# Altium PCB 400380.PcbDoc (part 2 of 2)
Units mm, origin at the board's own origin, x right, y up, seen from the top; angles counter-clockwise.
Board outline 48.52 x 76.32 mm, 4 copper layers (Top Layer, Mid-Layer 1, Mid-Layer 2, Bottom Layer), stack 1.542 mm thick; 122 components, 105 nets, 497 pads, 444 vias.
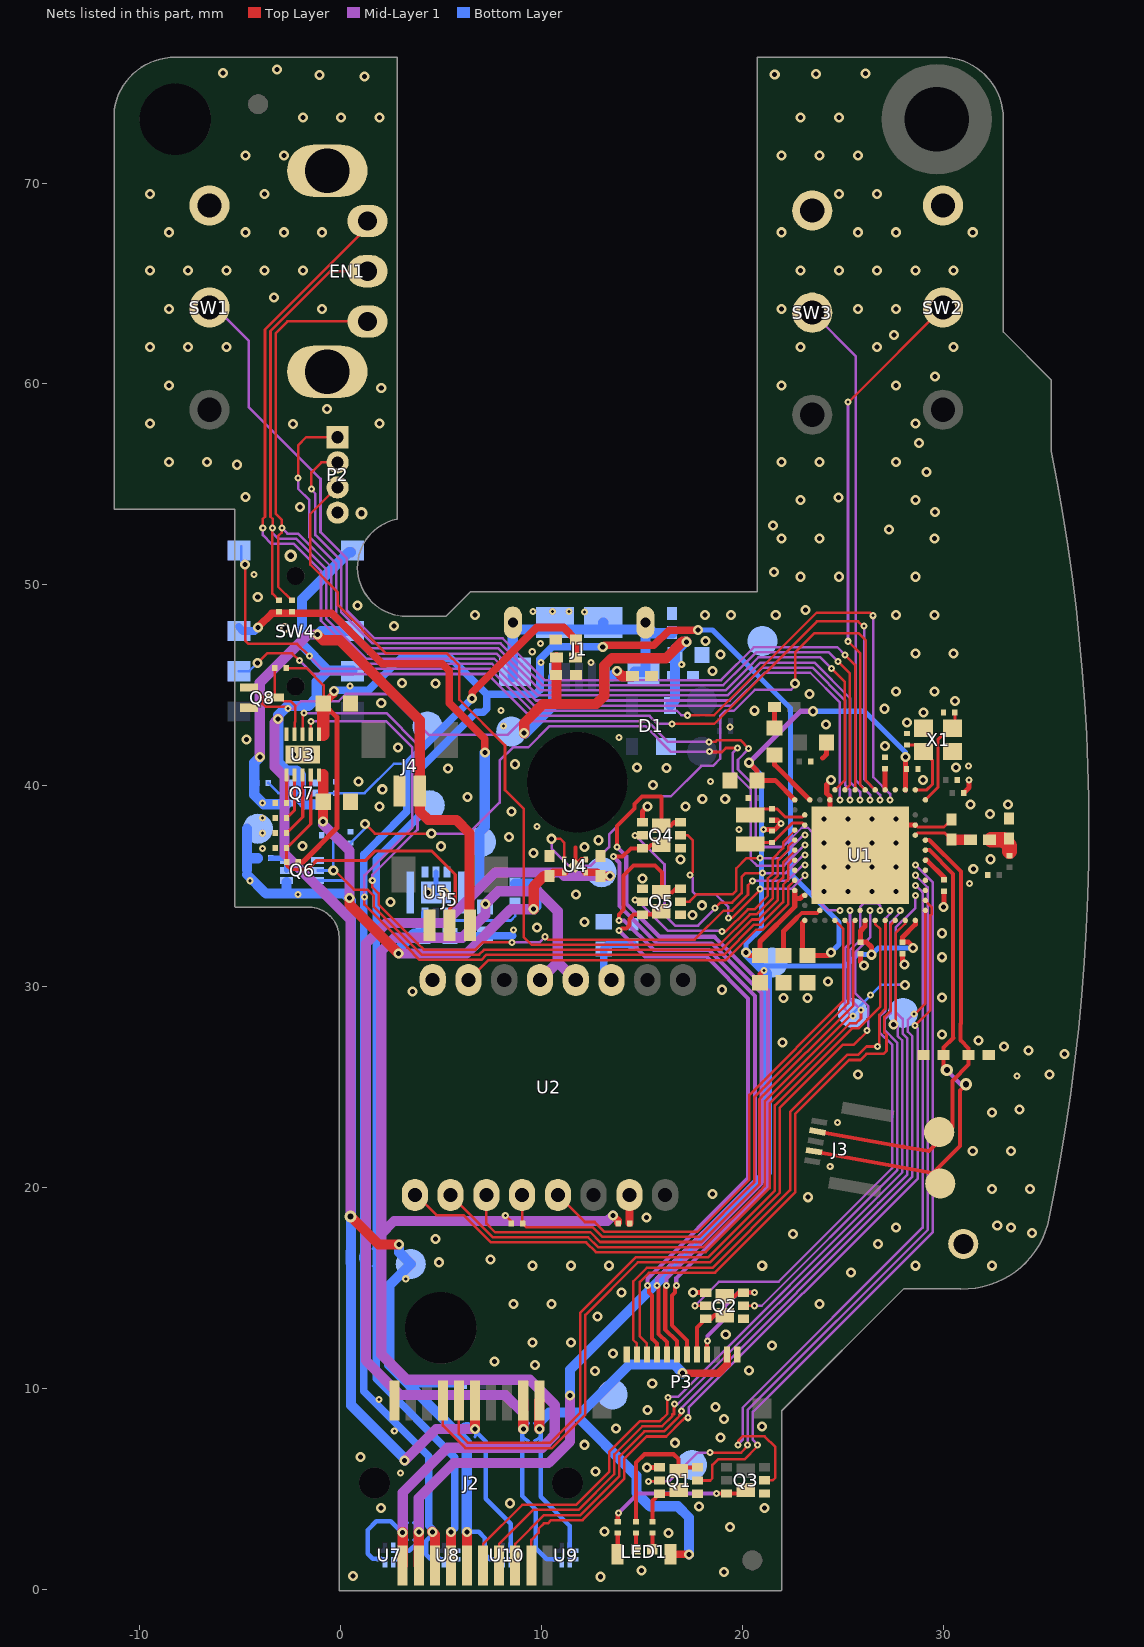
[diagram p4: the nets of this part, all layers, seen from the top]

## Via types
v1: diameter 0.5, hole 0.25, Top Layer to Bottom Layer, tented both sides, 311 vias
v2: diameter 0.35, hole 0.15, Top Layer to Mid-Layer 1, tented both sides, 102 vias
v3: diameter 0.35, hole 0.15, Top Layer to Mid-Layer 1, tented top, 26 vias
v4: diameter 0.61, hole 0.305, Top Layer to Mid-Layer 1, tented both sides, 3 vias
v5: diameter 0.61, hole 0.305, Top Layer to Bottom Layer, tented both sides, 2 vias

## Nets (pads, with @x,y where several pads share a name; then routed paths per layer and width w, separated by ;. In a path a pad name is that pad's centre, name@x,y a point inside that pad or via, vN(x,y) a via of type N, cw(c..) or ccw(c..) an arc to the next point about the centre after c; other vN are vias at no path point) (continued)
GND: C1.2 C2.2 C3.1 C4.1 C5.2 C6.2 C7.2 C8.2 C9.2 C10.1 C11.2 C12.2 C13.2 C14.2 C15.1 C16.2 C17.2 C18.2 C19.1 C20.2 C21.2 C22.2 C23.2 C24.1 C25.1 C26.1 C29.1 C30.1 C31.1 C32.1 C33.2 C34.1 C44.2 C45.2 C48.1 C49.1 D1.1 EN1.4 EN1.5 FB2.2 FB3.2 J2.20 J4.1 J5.1 P2.4 P3.1 P3.12 Q1.1 Q1.4 Q2.1 Q2.4 Q3.1 Q4.1 Q4.4 Q5.1 Q5.4 Q6.1 Q7.1 Q8.2 R4.1 R10.1 R11.1 R16.1 R26.2 R28.2 SW1.2 SW2.2 SW3.2 TP4.1 TP9.1 TP22.1 U1.74 U1.B7 U1.F23 U2.8 U3.5 U3.11 U4.2 U4.5 U5.2 U5.9 U7.2 U8.2 U9.2 U10.2 X1.2 X1.4 | length 23.8
  Top Layer w0.145: U1.F23@28.612,38.047 28.717,37.942 30.033,37.942 C3.1@30.413,38.323
  Top Layer w0.203: U4.5@11.684,36.014 11.693,36.023 11.693,36.912 11.709,36.928
  Top Layer w0.25: 24,41.373 24.187,41.561 C15.1@24.187,42.157 C15.1@24.187,42.411 ; v1(24.409,40.281) 24.204,40.076 24.204,39.629 24.362,39.471 U1.B7@24.362,39.297 24.362,38.047 v1(25.262,37.147) U1.74@25.862,36.547 v1(26.462,37.147) 27.362,38.047 U1.F23@28.612,38.047
  Top Layer w0.254: U4.5@11.693,36.023 12.009,36.339 U4.2@12.219,36.339 ; Q4.1@15.034,38.185 15.034,38.729 v1(15.279,38.974) ; v1(15.26,6.074) Q1.4@15.887,6.074 ; v1(17.551,14.783) 18.174,14.783 Q2.1@18.181,14.776 ; C6.2@20.88,30.197 20.88,30.62 21.067,30.807 v3(21.082,30.807) ; v3(21.057,37.817) 21.613,37.817 v3(21.921,38.125) 21.761,38.284 C17.2@21.489,38.284 ; C7.2@25.883,31.645 25.883,31.241 v1(26.061,31.064) ; C8.2@27.977,31.645 27.977,31.216 v1(28.078,31.114) ; v1(30.013,33.973) 30.037,33.997 C9.2@30.037,34.745 ; C10.1@31.019,39.646 31.293,39.92 v3(31.293,40.281)
  Bottom Layer w0.254: U5.9@4.75,34.693 U5.2@4.75,35.718
  Bottom Layer w0.381: C48.1@5.45,32.534 8.573,32.534
  other v1: 12.95,0.635 0.635,0.683 19.089,0.874 14.992,0.937 16.327,2.814 13.138,2.891 19.38,3.121 21.107,4.061 2.025,4.064 17.855,4.123 8.433,4.293 12.7,5.864 0.991,6.589 12.141,7.203 16.653,7.303 18.926,7.569 13.716,8.024 20.98,8.121 19.089,8.494 15.291,8.938 18.669,9.09 15.519,10.262 12.675,10.871 20.345,10.893 9.674,11.171 7.671,11.351 13.575,11.735 21.488,12.138 9.564,12.304 11.469,12.304 19.178,12.7 12.802,13.589 8.611,14.209 10.516,14.209 23.851,14.209 13.979,14.783 25.4,15.773 9.564,16.114 11.469,16.114 13.374,16.114 20.994,16.114 28.614,16.114 32.424,16.114 4.913,16.286 7.468,16.434 26.746,17.193 4.724,17.433 22.53,17.688 34.417,17.751 27.661,18.019 33.376,18.019 32.69,18.107 15.228,18.517 23.266,19.523 18.517,19.685 32.424,19.924 34.329,19.924 31.471,21.829 33.376,21.829 32.424,23.734 33.807,23.898 25.756,25.639 35.281,25.639 36.043,26.641 34.239,26.819 33.02,27.022 21.996,27.225 31.75,27.327 29.947,27.632 22.048,29.443 23.237,29.443 29.947,29.461 3.581,29.766 18.999,29.849 24.258,30.251 29.947,31.467 29.947,32.661 9.784,32.951 12.148,33.226 17.529,33.579 18.001,34.054 2.499,34.214 11.735,34.595 4.35,34.693 5.15,34.693 24.062,34.747 25.262,34.747 26.462,34.747 27.662,34.747 15.034,35.376 31.496,35.862 24.062,35.947 25.262,35.947 26.462,35.947 27.662,35.947 16.916,36.335 32.36,36.344 9.621,36.649 12.141,36.954 5.004,36.991 -1.88,37.008 24.062,37.147 27.662,37.147 12.852,37.289 8.382,37.462 24.062,38.347 25.262,38.347 26.462,38.347 27.662,38.347 32.335,38.587 8.509,38.723 1.944,38.974 17.184,38.974 31.369,39.062 33.224,39.065 18.009,39.341 19.152,39.341 6.325,39.446 2.083,39.827 15.559,40.046 0.901,40.208 28.985,40.279 5.359,40.85 16.231,40.879 14.757,40.916 30.633,40.919 8.686,41.072 -2.339,41.548 -1.448,41.556 2.855,41.91 27.102,41.986 -4.673,42.313 24.156,43.052 28.198,43.154 29.02,43.637 20.599,43.736 27.076,43.834 2.032,44.111 30.584,44.218 23.343,44.574 27.661,44.689 29.566,44.689 4.729,45.082 3.075,45.116 18.517,45.717 18.923,46.53 28.614,46.594 30.519,46.594 18.161,47.215 -2.769,47.85 2.667,47.952 6.706,48.499 18.136,48.499 19.431,48.511 21.666,48.511 27.661,48.499 29.566,48.499 23.139,48.739 0.852,48.968 -4.115,49.403 22.899,50.404 24.804,50.404 28.614,50.404 21.59,50.644 21.946,52.309 23.851,52.309 29.566,52.309 27.305,52.753 21.539,52.956 29.591,53.616 -2.003,53.877 22.899,54.214 28.614,54.214 24.79,54.353 -4.724,54.378 29.159,55.623 -5.156,55.978 -8.534,56.119 -6.629,56.119 21.946,56.119 23.851,56.119 27.661,56.119 28.804,57.071 -2.362,58.01 -9.486,58.024 1.944,58.024 28.614,58.024 -0.663,58.75 2.032,59.788 -8.534,59.929 21.946,59.929 27.661,59.929 29.591,60.373 -9.486,61.834 -7.581,61.834 -5.676,61.834 22.899,61.834 26.709,61.834 30.519,61.834 27.559,62.43 -8.534,63.739 -0.914,63.739 21.946,63.739 25.756,63.739 27.661,63.739 -3.316,64.31 -9.486,65.644 -7.581,65.644 -5.676,65.644 -3.771,65.644 -1.866,65.644 22.899,65.644 24.804,65.644 26.709,65.644 28.614,65.644 30.519,65.644 -8.534,67.549 -4.724,67.549 -2.819,67.549 -0.914,67.549 21.946,67.549 25.756,67.549 27.661,67.549 31.471,67.549 -9.486,69.454 -3.771,69.454 24.804,69.454 26.709,69.454 -4.724,71.359 -2.819,71.359 21.946,71.359 23.851,71.359 25.756,71.359 -1.866,73.264 0.039,73.264 1.944,73.264 22.899,73.264 24.804,73.264 1.194,75.308 -1.041,75.384 21.615,75.409 23.673,75.435 26.137,75.46 -5.842,75.486 -3.15,75.638
  other v2: 3,5.8 2.68,7.896 1.915,9.446 3.251,15.465 24.378,21.052 24.748,23.232 33.681,25.561 26.391,29.591 8.611,32.817 -2.108,34.595 31.319,35.128 -4.496,35.274 -3.886,36.888 -3.886,37.639 9.779,37.973 -3.886,38.389 -3.886,39.139 18.416,40.205 13.859,42.393 19.392,42.916 8.128,42.979 8,43.758 0.483,44.974 16.987,46.045 9.988,46.142 12.472,46.145 9.547,46.671 9.952,47.081 12.143,48.639 9.594,48.666 10.564,48.679 11.374,48.666 -4.293,50.517
  other v3: 19.837,37.821 31.267,40.992
  other v5: -2.474,51.447 1.046,53.565
LED2_B_LOW: P3.4 Q5.3 | length 30.7
  Top Layer w0.203: v2(13.868,32.788) 13.897,32.788 14.005,32.896 14.226,32.896 14.39,33.059 14.39,33.379 14.597,33.586 Q5.3@15.034,33.586 15.476,33.586 15.651,33.761 Q5.3@15.979,33.761 Q5.3@16.129,33.761 ; v2(15.284,15.135) 15.358,15.062 15.358,14.774 15.505,14.627 15.505,12.482 15.75,12.237 P3.4@15.75,11.7
  Mid-Layer 1 w0.203: v2(13.868,32.788) 15.16,31.496 18.209,31.496 18.336,31.369 20.295,29.41 20.295,20.473 15.284,15.463 v2(15.284,15.135)
LED2_G_LOW: P3.5 Q5.6 | length 35
  Top Layer w0.203: v2(13.868,33.299) 13.868,33.604 14.097,33.833 14.097,35.528 14.592,36.023 15.663,36.023 16.002,35.684 16.002,34.838 16.144,34.696 16.504,34.696 16.693,34.886 Q5.6@16.924,34.886 Q5.6@17.074,34.886 ; v2(15.761,15.135) 15.835,15.062 15.835,12.725 16.25,12.31 P3.5@16.25,11.7
  Mid-Layer 1 w0.203: v2(13.868,33.299) 14.122,33.299 15.596,31.826 18.345,31.826 18.472,31.699 20.625,29.547 20.625,20.336 20.431,20.143 15.761,15.473 v2(15.761,15.135)
LED2_R_LOW: P3.6 Q4.3 | length 34.3
  Top Layer w0.203: v2(13.589,36.474) 14.042,36.474 14.453,36.885 Q4.3@15.034,36.885 15.294,36.885 15.469,37.06 Q4.3@15.979,37.06 ; v2(16.238,15.135) 16.165,15.062 16.165,12.95 16.75,12.365 P3.6@16.75,11.7
  Mid-Layer 1 w0.203: v2(13.589,36.474) 13.894,36.17 13.894,34.016 15.754,32.156 18.482,32.156 18.609,32.029 20.955,29.684 20.955,20.2 16.238,15.483 v2(16.238,15.135)
LED3_B_LOW: P3.7 Q4.6 | length 38.7
  Top Layer w0.203: v2(13.767,36.957) 13.767,37.998 14.636,38.868 14.636,39.096 15.011,39.472 15.951,39.472 15.979,39.444 Q4.6@15.979,38.01 16.439,38.01 16.614,38.185 Q4.6@16.868,38.185 ; v2(16.716,15.135) 16.642,15.062 16.642,14.774 16.495,14.627 16.495,13.15 17.25,12.395 P3.7@17.25,11.7
  Mid-Layer 1 w0.203: v2(13.767,36.957) 14.224,36.5 14.224,34.153 15.891,32.487 18.619,32.487 18.746,32.36 21.285,29.82 21.285,20.063 16.716,15.493 v2(16.716,15.135)
NetC3_2: C3.2 L1.1 U1.H23 | length 2.9
  Top Layer w0.145: U1.H23@28.612,37.547 28.717,37.652 30.082,37.652 C3.2@30.416,37.318
  Top Layer w0.508: C3.2@30.416,37.318 L1.1@31.31,37.318
NetC9_1: C9.1 U1.N24 | length 1.4
  Top Layer w0.25: U1.N24@29.112,36.297 29.188,36.297 30.037,35.449 C9.1@30.037,35.315
NetC13_1: C13.1 U1.A18 | length 1
  Top Layer w0.25: U1.A18@27.112,39.797 C13.1@27.112,40.845
NetC20_1: C20.1 U1.AC5 | length 3.5
  Top Layer w0.184: 22.704,33.42 22.957,33.672 23.736,33.672 U1.AC5@23.862,33.797
  Top Layer w0.25: C20.1@22.062,31.547 22.062,32.777 22.704,33.42
NetC22_1: C22.1 U3.6 | length 1.4
  Top Layer w0.152: C22.1@-2.682,39.137 -2.676,39.143 U3.6@-2.676,40.541
NetC24_2: C24.2 C25.2 U2.3 | length 3.3
  Bottom Layer w0.381: U2.3@13.494,30.337 13.106,30.724 C25.2@13.106,31.885 13.332,32.11 C24.2@14.58,32.11
NetC29_2: C29.2 C31.2 C32.2 D1.4 FB1.1 J1.1 TP1.1 | length 20.5
  Top Layer w0.508: v1(9.144,42.618) 9.144,43.122 10.098,44.076 12.737,44.076 13.132,44.472 13.132,45.974 13.51,46.352 16.205,46.352 17.018,47.165 v1(17.221,47.165) ; 10.755,44.102 FB1.1@10.755,46.393
  Bottom Layer w0.508: v1(9.144,42.618) 9.195,42.618 10.592,44.015 J1.1@10.592,45.408 ; D1.4@16.411,44.004 16.648,44.24 16.648,46.794 16.777,46.923 16.918,46.923 17.159,47.165 v1(17.221,47.165)
NetFB2_1: FB2.1 J1.5 | length 1.6
  Top Layer w0.508: v1(13.767,45.702) 14.021,45.448 14.522,45.448 FB2.1@14.536,45.463
  Bottom Layer w0.508: J1.5@13.181,45.448 13.513,45.448 v1(13.767,45.702)
NetFB3_1: FB3.1 J1.6@8.581,48.123 J1.6@8.681,45.673 J1.6@10.681,48.123 J1.6@13.081,48.123 J1.6@15.081,45.673 J1.6@15.181,48.123 | length 13.6
  Bottom Layer w0.508: J1.6@8.579,45.423 8.579,47.773 J1.6@13.081,47.773 ; J1.6@13.081,48.123 J1.6@13.081,47.773 ; J1.6@14.649,45.673 J1.6@15.081,45.673 15.181,45.773 15.181,47.992 ccw(c15.483,48.027) J1.6@15.483,47.723 ; J1.6@15.179,47.773 J1.6@13.081,47.773 ; J1.6@15.483,47.596 FB3.1@16.51,47.596
NetL2_1: L2.1 L3.2 | length 1.1
  Top Layer w0.25: L2.1@21.612,42.872 L3.2@21.612,43.922
NetL2_2: L2.2 U1.B3 | length 2.9
  Top Layer w0.25: L2.2@21.612,41.522 21.612,41.047 U1.B3@23.362,39.297
NetLED1_1: LED1.1 R9.2 | length 0.7
  Top Layer w0.127: LED1.1@15.516,2.131 LED1.1@15.529,2.131
  Top Layer w0.203: LED1.1@15.529,2.131 R9.2@15.529,2.811
NetLED1_2: LED1.2 R8.2 | length 0.8
  Top Layer w0.203: LED1.2@14.704,2.004 14.716,2.017 R8.2@14.716,2.811
NetLED1_3: LED1.3 R7.2 | length 1.1
  Top Layer w0.203: LED1.3@13.789,1.75 13.802,1.763 R7.2@13.802,2.811
NetP3_8: P3.8 Q2.3 | length 3
  Top Layer w0.203: P3.8@17.75,11.7 17.75,13.045 Q2.3@18.181,13.476 18.454,13.476 18.629,13.651 Q2.3@19.126,13.651
NetP3_9: P3.9 Q2.6 | length 6.1
  Top Layer w0.203: P3.9@18.25,11.7 18.25,12.353 v2(18.263,12.365) ; Q2.6@19.126,14.601 19.63,14.601 19.805,14.776 Q2.6@20.071,14.776 20.078,14.783 v2(20.599,14.783)
  Mid-Layer 1 w0.203: v2(18.263,12.365) 18.263,12.609 19.126,13.473 19.126,14.097 19.812,14.783 v2(20.599,14.783)
NetQ1_3: Q1.3 R8.1 | length 6.9
  Top Layer w0.203: R8.1@14.716,3.381 14.716,6.318 15.129,6.731 16.586,6.731 16.832,6.485 Q1.3@16.832,5.899 17.007,6.074 Q1.3@17.777,6.074
NetQ1_6: Q1.6 R9.1 | length 2.1
  Top Layer w0.203: R9.1@15.529,3.381 15.529,4.416 Q1.6@15.887,4.774 ; Q1.6@15.887,4.744 Q1.6@16.455,4.744
NetQ3_6: Q3.6 R7.1 | length 7.3
  Top Layer w0.203: R7.1@13.802,3.381 13.802,3.775 v2(13.837,3.81) ; v2(18.72,4.78) 19.179,4.78 19.2,4.801 Q3.6@19.221,4.78 19.991,4.78 Q3.6@20.166,4.955
  Mid-Layer 1 w0.203: v2(13.837,3.81) 14.807,4.78 v2(18.72,4.78)
NetQ6_3: Q6.3 R27.1 | length 2.2
  Bottom Layer w0.127: Q6.3@-1.13,35.285 0.36,35.285 0.494,35.419 R27.1@0.494,35.983
NetQ6_5: Q6.5 Q6.6 R24.2 | length 1.3
  Bottom Layer w0.254: R24.2@-3.474,36.395 -2.79,36.395 Q6.6@-2.68,36.285 Q6.5@-2.68,35.785
NetQ7_5: Q7.5 Q7.6 R14.1 | length 1.6
  Bottom Layer w0.127: R14.1@-3.586,40.139 -3.081,39.634 Q7.5@-2.693,39.634 Q7.6@-2.693,40.134 Q7.6@-2.698,40.139
NetQ8_3: Q8.3 R15.1 U3.4 | length 4.1
  Top Layer w0.127: R15.1@-3.266,45.857 -3.266,44.439 -3.27,44.435 -3.048,44.435 -2.822,44.208 -2.474,44.208 -2.472,44.206 -2.465,44.206 -2.251,43.992 -2.251,43.18 -2.276,43.155 U3.4@-2.276,42.571
NetR2_1: R2.1 U2.15 | length 1.4
  Top Layer w0.127: R2.1@14.383,18.233 R2.1@14.407,18.209
  Top Layer w0.381: R2.1@14.383,18.233 U2.15@14.383,19.637
NetR10_2: R10.2 U3.7 | length 2.3
  Top Layer w0.152: R10.2@-2.682,38.389 -2.276,38.795 U3.7@-2.276,40.541
NetR11_2: R11.2 U3.8 | length 3.2
  Top Layer w0.152: R11.2@-2.682,37.641 -1.876,38.447 U3.8@-1.876,40.541
NetR13_1: R13.1 U5.4 | length 4.2
  Bottom Layer w0.127: U5.4@5.3,33.668 5.672,33.296 8.48,33.296 8.691,33.507 R13.1@8.691,34.036
NetU5_1: U5.1 U5.7
NTC: J5.2 R3.1 R4.2 U3.9 | length 17
  Top Layer w0.152: U3.9@-1.476,40.541 -1.476,38.099 R4.2@-2.682,36.893 -2.682,36.216 R3.1@-2.673,36.207 -2.673,36.023 -2.489,35.839 -1.627,35.839 -1.177,36.289 1.262,36.289 1.735,36.761 4.535,36.761 5.715,35.581 5.715,34.172 5.44,33.897 5.44,33.067 J5.2@5.44,33.057
P0.00/XL1: C17.1 U1.D2 X2.1 | length 3.1
  Top Layer w0.145: X2.1@20.397,38.545 20.706,38.854 C17.1@21.489,38.854 21.725,38.854 22.137,38.442 23.007,38.442 U1.D2@23.112,38.547
P0.01/XL2: C18.1 U1.F2 X2.2 | length 3.2
  Top Layer w0.145: X2.2@20.397,37.095 20.478,37.177 21.514,37.177 22.49,38.152 23.007,38.152 U1.F2@23.112,38.047
P0.02/AIN0: SW1.3 U1.A12 | length 51.8
  Top Layer w0.127: v2(25.109,46.518) 25.612,46.016 U1.A12@25.612,39.797
  Mid-Layer 1 w0.127: SW1.3@-6.216,63.797 -4.572,62.152 -4.572,58.852 -0.991,55.27 -0.991,52.629 0.305,51.333 0.305,48.739 1.701,47.343 8.076,47.343 10.16,45.26 18.948,45.26 20.584,46.895 24.733,46.895 v2(25.109,46.518)
P0.03/AIN1: EN1.3 R29.1 U1.B13 | length 58.8
  Top Layer w0.127: R29.1@-2.42,49.228 -3.099,49.906 -3.099,52.426 -2.921,52.603 -2.921,52.819 v2(-2.911,52.829) -2.911,53.228 -3.226,53.543 -3.226,62.519 -2.634,63.11 EN1.3@1.647,63.11
  Mid-Layer 1 w0.127: v2(-2.911,52.829) -2.635,52.553 -2.108,52.553 -0.457,50.902 -0.457,48.424 1.385,46.581 7.76,46.581 9.844,44.498 19.264,44.498 20.9,46.133 23.594,46.133 25.37,44.357 25.37,40.192 25.862,39.7 v3(25.862,39.297)
P0.04/AIN2: P2.3 U1.J1 | length 46
  Top Layer w0.127: P2.3@-0.141,54.847 -0.159,54.864 -1.503,53.52 -1.503,51.003 -0.127,49.628 -0.127,48.997 2.275,46.595 5.298,46.595 5.918,45.974 5.918,44.283 8.192,42.009 8.192,39.789 9.119,38.862 9.119,32.485 9.514,32.089 18.87,32.089 20.381,33.6 20.705,33.6 21.522,34.416 21.522,35.285 21.776,35.539 21.776,36.284 22.284,36.792 22.284,36.969 U1.J1@22.612,37.297
P0.05/AIN3: R27.2 R28.1 U1.K2 | length 34.1
  Top Layer w0.127: v1@1.101,38.232 1.715,37.617 v1(4.521,37.617) ; v1@1.173,38.1 v1(1.219,38.1) ; v2(18.364,41.704) 18.386,41.681 18.981,41.681 19.181,41.881 v2(19.761,41.881)
  Mid-Layer 1 w0.127: v1(4.521,37.617) 6.375,37.617 7.925,39.167 7.925,41.25 8.585,41.91 9.347,41.91 10.404,42.967 15.173,42.967 16.437,41.704 v2(18.364,41.704) ; v2(19.761,41.881) 19.533,41.653 19.533,40.698 20.422,39.809 20.422,36.334 20.726,36.029 22.077,36.029 23.095,37.047 v3(23.112,37.047)
  Bottom Layer w0.127: R27.2@0.494,36.604 R28.1@0.494,37.151 1.219,37.877 v1(1.219,38.1)
P0.06: Q6.2 R26.1 U1.L1 | length 30.7
  Top Layer w0.127: v1@-0.394,35.797 -0.288,35.797 0.676,34.833 1.353,34.833 1.651,34.536 1.651,33.989 3.588,32.052 3.588,32.05 4.044,31.594 6.905,31.594 7.146,31.835 18.975,31.835 20.486,33.346 20.811,33.346 21.776,34.311 21.776,35.18 22.03,35.434 22.03,36.179 22.612,36.761 U1.L1@22.612,36.797
  Bottom Layer w0.127: Q6.2@-1.13,35.785 v1(-0.356,35.785) -0.356,36.485 -0.35,36.491 R26.1@-0.35,37.538
P0.07: Q4.2 U1.M2 | length 14.1
  Top Layer w0.127: v2(14.661,37.527) 15.026,37.527 Q4.2@15.034,37.535 ; v2(18.644,33.909) 18.923,34.188 19.487,34.188 19.964,34.665 19.964,35.458 20.164,35.658 v2(21.006,35.658)
  Mid-Layer 1 w0.127: v2(14.661,37.527) 14.661,37.56 16.129,36.091 16.129,33.579 16.662,33.045 17.805,33.045 18.644,33.884 v2(18.644,33.909) ; v2(21.006,35.658) 22.157,35.658 23.046,36.547 v3(23.112,36.547)
P0.08: U1.N1 U3.2 | length 40.6
  Top Layer w0.127: U3.2@-1.476,42.571 -1.473,42.574 v2(-1.473,43.205) ; v2(1.194,34.468) 1.194,34.087 3.334,31.947 3.334,31.945 3.939,31.34 7.01,31.34 7.251,31.581 19.081,31.581 20.591,33.092 20.916,33.092 22.03,34.206 22.03,35.075 22.284,35.329 22.284,36.074 22.507,36.297 U1.N1@22.612,36.297
  Mid-Layer 1 w0.127: v2(-1.473,43.205) 2.286,43.205 3.581,41.91 3.581,37.922 1.194,35.535 v2(1.194,34.468)
P0.09/NFC1: C33.1 J3.2 TP7.1 U1.L24 | length 24.3
  Top Layer w0.203: J3.2@23.569,21.808 TP7.1@29.469,20.739 ; U1.L24@29.112,36.797 29.313,36.797 30.492,35.619 30.492,27.456 30.499,27.448 30.024,26.973 C33.1@30.024,26.601 30.024,26.015 v4(30.182,25.857) ; TP7.1@29.485,20.723 30.832,22.07 30.832,24.841 v4(31.137,25.146)
  Mid-Layer 1 w0.203: v4(30.182,25.857) 30.182,25.835 30.871,25.146 v4(31.137,25.146)
P0.10/NFC2: C34.2 J3.4 TP8.1 U1.J24 | length 22.9
  Top Layer w0.203: J3.4@23.743,22.792 28.024,22.034 29.291,21.818 30.455,22.981 30.455,25.318 31.267,26.131 C34.2@31.267,26.601 31.267,26.93 30.876,27.321 30.876,27.323 30.863,27.336 30.863,28.159 30.877,28.172 30.877,35.726 29.305,37.297 U1.J24@29.112,37.297
P0.11: Q4.5 U1.T2 | length 10.7
  Top Layer w0.127: Q4.5@16.924,37.535 17.292,37.535 17.53,37.297 17.53,35.691 v2(17.399,35.56) ; v2(19.304,33.426) 19.489,33.426 20.882,34.82 v2(20.882,34.874)
  Mid-Layer 1 w0.127: v2(17.399,35.56) 17.53,35.429 17.53,34.745 17.679,34.596 18.681,34.596 19.304,33.973 v2(19.304,33.426) ; v2(20.882,34.874) 22.439,34.874 v3(23.112,35.547)
P0.12: U1.U1 U2.7 | length 18.8
  Top Layer w0.127: U2.7@6.374,30.337 7.364,31.327 19.186,31.327 20.697,32.838 21.021,32.838 22.284,34.101 22.284,34.969 U1.U1@22.612,35.297
P0.13: U1.AD8 U2.13 | length 26.4
  Top Layer w0.127: U2.13@10.824,19.637 12.171,18.289 12.651,18.289 13.138,17.802 17.758,17.802 20.349,20.393 20.349,24.614 25.019,29.284 25.019,32.89 U1.AD8@24.612,33.297
P0.14: Q8.1 U1.AC9 | length 41
  Top Layer w0.127: Q8.1@-4.551,44.884 -4.301,44.884 -3.892,44.475 -3.892,44.105 -3.724,43.936 -2.712,43.936 v2(-2.616,43.84) ; v2(18.339,42.186) 18.666,42.186 18.75,42.271 19.905,42.271 v2(20.32,41.856)
  Mid-Layer 1 w0.127: v2(-2.616,43.84) -2.337,43.84 -1.969,44.208 -0.09,44.208 0.271,44.568 2.371,44.568 4.394,42.545 8.331,42.545 9.007,43.221 15.279,43.221 16.314,42.186 v2(18.339,42.186) ; v2(20.32,41.856) 20.32,41.831 19.787,41.297 19.787,40.815 20.676,39.926 20.676,37.284 21.006,36.954 22.001,36.954 22.96,37.913 23.263,37.913 23.477,37.699 23.477,34.584 24.264,33.797 v3(24.862,33.797)
P0.15: R1.1 U1.AD10 U2.12 | length 29.4
  Top Layer w0.127: U2.12@9.044,19.637 9.044,18.238 R1.1@9.073,18.209 9.247,18.035 12.545,18.035 13.032,17.548 17.863,17.548 20.286,19.97 20.603,20.288 20.603,24.508 25.273,29.178 25.273,33.136 U1.AD10@25.112,33.297
P0.16: U1.AC11 U2.10 | length 33.9
  Top Layer w0.127: U2.10@5.484,19.637 7.593,17.527 12.335,17.527 12.822,17.04 18.074,17.04 20.873,19.84 21.111,20.077 21.111,24.298 25.359,28.546 v2(25.517,28.546)
  Mid-Layer 1 w0.127: v3(25.362,33.797) 25.362,32.173 25.112,31.924 25.112,28.877 25.444,28.546 v2(25.517,28.546)
P0.17: U1.AD12 U2.11 | length 31.7
  Top Layer w0.127: U2.11@7.264,19.637 7.264,18.216 7.698,17.781 12.44,17.781 12.927,17.294 17.969,17.294 20.857,20.183 20.857,24.403 25.527,29.073 25.527,33.213 U1.AD12@25.612,33.297
P0.18/RESET: U1.AC13
P0.19: J2.17 U1.AC15 | length 43.4
  Top Layer w0.127: J2.17@5.1,9.4 5.1,8.156 6.221,7.036 10.52,7.036 12.192,8.708 12.192,13.673 14.797,16.278 18.389,16.278 21.873,19.762 21.873,23.982 25.005,27.114 25.558,27.114 26.254,27.81 26.254,27.876 v2@26.264,27.886
  Mid-Layer 1 w0.127: v2@26.274,27.896 26.274,29.028 25.62,29.681 25.62,31.713 26.362,32.455 v3(26.362,33.797)
  other v2: 26.213,27.81
P0.20: J2.16 U1.AD16 | length 41.6
  Top Layer w0.127: J2.16@5.9,9.4 5.9,7.739 6.343,7.296 10.421,7.296 11.938,8.813 11.938,13.778 14.692,16.532 18.284,16.532 21.619,19.867 21.619,24.088 25.458,27.927 25.788,27.927 26.873,29.012 26.873,32.864 26.612,33.126 U1.AD16@26.612,33.297
P0.21: U1.AC17 U2.9 | length 38
  Top Layer w0.127: U2.9@3.704,19.637 3.768,19.637 4.771,18.633 6.128,18.633 7.488,17.273 8.255,17.273 12.23,17.273 12.717,16.786 18.179,16.786 21.365,19.972 21.365,24.193 25.353,28.181 25.669,28.181 25.908,28.419 v2(25.908,28.851)
  Mid-Layer 1 w0.127: v2(25.908,28.851) 25.366,29.393 25.366,31.819 25.862,32.314 25.862,33.964 26.061,34.163 26.735,34.163 26.862,34.036 v3(26.862,33.797)
P0.22: P3.2 U1.AD18 | length 29.4
  Top Layer w0.127: P3.2@14.75,11.7 14.75,12.25 14.575,12.425 14.575,15.337 15.246,16.008 18.514,16.008 22.381,19.875 22.381,23.772 25.215,26.606 25.768,26.606 26.188,27.026 v2(26.721,27.026) 26.822,27.127 26.822,28.602 27.127,28.907 27.127,33.282 U1.AD18@27.112,33.297
P0.23: Q2.2 U1.AC19 | length 26.5
  Top Layer w0.127: v2(17.645,14.122) 18.134,14.122 18.156,14.101 Q2.2@18.181,14.126
  Mid-Layer 1 w0.127: v2(17.645,14.122) 18.839,15.316 21.804,15.316 27.453,20.966 27.453,27.114 26.839,27.728 26.839,28.509 27.124,28.794 27.124,33.395 27.362,33.632 v3(27.362,33.797)
P0.24: P3.3 U1.AD20 | length 29.8
  Top Layer w0.127: P3.3@15.25,11.7 15.25,12.25 14.9,12.6 14.9,15.303 15.351,15.754 18.619,15.754 18.639,15.773 18.644,15.773 22.635,19.765 22.635,23.667 25.32,26.352 25.874,26.352 26.178,26.657 27.025,26.657 27.178,26.81 27.178,27.619 27.076,27.721 27.076,28.497 27.381,28.802 27.381,33.067 U1.AD20@27.612,33.297
P0.25: Q2.5 U1.AC21 | length 23.9
  Top Layer w0.127: Q2.5@20.071,14.126 20.075,14.122 v2(20.599,14.122)
  Mid-Layer 1 w0.127: v2(20.599,14.122) 20.969,14.122 27.707,20.861 27.707,27.219 27.093,27.833 27.093,28.403 27.378,28.688 27.378,33.204 27.862,33.687 v3(27.862,33.797)
P0.26: Q5.2 U1.G1 | length 12.4
  Top Layer w0.127: v2(14.656,34.315) 14.735,34.236 Q5.2@15.034,34.236 Q5.2@15.184,34.236 ; v2(18.981,32.741) 19.163,32.741 20.276,33.854 20.6,33.854 21.268,34.521 21.268,35.39 21.522,35.644 21.522,36.39 22.03,36.898 22.03,37.179 22.612,37.761 U1.G1@22.612,37.797
  Mid-Layer 1 w0.127: v2(14.656,34.315) 14.808,34.163 14.916,34.163 16.287,32.791 18.92,32.791 18.971,32.741 v2(18.981,32.741)
P0.27: Q5.5 U1.H2 | length 8.1
  Top Layer w0.127: Q5.5@17.074,34.236 17.374,34.236 17.733,34.595 19.507,34.595 19.71,34.798 19.71,35.895 20.214,36.398 v2(20.879,36.398)
  Mid-Layer 1 w0.127: v2(20.879,36.398) 21.891,36.398 21.894,36.395 23.046,37.547 v3(23.112,37.547)
P0.28/AIN4: EN1.2 R30.1 U1.B11 | length 60
  Top Layer w0.127: R30.1@-3.055,49.228 -3.388,49.56 v2(-3.388,52.829) -3.378,52.839 -3.378,53.289 -3.48,53.391 -3.48,62.624 -0.494,65.61 EN1.2@1.647,65.61
  Mid-Layer 1 w0.127: v2(-3.388,52.829) -3.388,52.588 -3.099,52.299 -2.213,52.299 -0.711,50.796 -0.711,48.318 1.28,46.327 7.655,46.327 9.739,44.244 19.369,44.244 21.005,45.879 23.489,45.879 25.116,44.252 25.116,40.043 25.362,39.797 v3(25.362,39.297)
P0.29/AIN5: P2.2 U1.A10 | length 43
  Top Layer w0.127: v2(-1.448,54.762) -1.448,55.601 -0.952,56.097 P2.2@-0.141,56.097 ; v2@24.744,46.209 v2(24.772,46.181) 25.358,45.595 25.358,40.043 U1.A10@25.112,39.797
  Mid-Layer 1 w0.127: v2(-1.448,54.762) -1.448,54.737 -1.245,54.534 -1.245,52.476 0.051,51.181 0.051,48.634 1.595,47.089 7.971,47.089 9.013,46.047 10.055,45.006 19.054,45.006 20.051,46.003 20.689,46.641 24.312,46.641 v2(24.772,46.181)
P0.30/AIN6: EN1.1 U1.B9 | length 57.7
  Top Layer w0.127: v2(-3.865,52.829) -3.865,53.279 -3.754,53.391 -3.754,62.709 EN1.1@1.647,68.11
  Mid-Layer 1 w0.127: v2(-3.865,52.829) -3.861,52.824 -3.861,52.476 -3.429,52.045 -2.319,52.045 -0.965,50.691 -0.965,48.213 1.175,46.073 7.55,46.073 9.634,43.99 19.474,43.99 21.11,45.625 23.383,45.625 24.862,44.147 v3(24.862,39.297)
P0.31/AIN7: P2.1 U1.A8 | length 45
  Top Layer w0.127: v2(-2.103,55.321) -2.103,56.946 -1.702,57.347 P2.1@-0.141,57.347 ; v2(24.435,45.844) 25.104,45.175 25.104,40.289 U1.A8@24.612,39.797
  Mid-Layer 1 w0.127: v2(-2.103,55.321) -2.103,54.782 -1.549,54.229 -1.549,52.375 -0.203,51.029 -0.203,48.529 1.49,46.835 7.866,46.835 8.759,45.942 9.949,44.752 19.159,44.752 20.305,45.898 20.794,46.387 23.892,46.387 v2(24.435,45.844)
P1.00: J2.6 TP15.1 U1.AD22 | length 43.5
  Top Layer w0.127: J2.6@7.1,1.2 7.1,2.264 9.05,4.213 11.736,4.213 13.374,5.851 13.374,6.833 14.919,8.378 15.9,8.378 16.265,8.743 16.265,9.532 v2(16.293,9.561) ; v2(27.61,28.089) 27.635,28.115 27.635,32.663 28.112,33.14 U1.AD22@28.112,33.297
  Mid-Layer 1 w0.127: v2(16.293,9.561) 16.322,9.589 16.795,9.589 27.961,20.755 27.961,27.324 27.727,27.558 27.727,27.998 27.635,28.089 v2(27.61,28.089)
  other v1: 27.534,28.115
P1.01: J2.7 TP16.1 U1.Y23 | length 48.1
  Top Layer w0.127: J2.7@7.9,1.2 7.9,2.264 9.596,3.959 11.841,3.959 13.628,5.746 13.628,6.727 15.024,8.124 16.006,8.124 16.519,8.638 16.519,8.728 16.609,8.728 16.603,8.735 16.603,9.037 16.631,9.066 v2(16.631,9.223)
  Mid-Layer 1 w0.127: v2(16.631,9.223) 16.788,9.223 26.781,19.216 28.215,20.65 28.215,27.429 27.981,27.664 27.981,28.404 27.632,28.753 27.632,30.096 ; v1(28.092,30.096) 27.632,30.096 ; v3(28.612,34.547) 28.612,33.92 27.632,32.941 27.632,32.768 27.632,30.096
  Bottom Layer w0.127: TP16.1@25.5,28.7 26.896,30.096 v1(28.092,30.096)
P1.02: U1.W24
P1.03: Q3.2 U1.V23 | length 36.3
  Top Layer w0.127: v2(19.792,7.185) 19.792,7.397 20.015,7.62 21.111,7.62 21.646,7.085 21.646,5.562 21.514,5.43 Q3.2@21.111,5.43
  Mid-Layer 1 w0.127: v2(19.792,7.185) 19.792,7.225 20.015,7.448 20.015,9.046 28.977,18.009 28.977,33.689 28.977,34.699 28.966,34.71 28.966,34.721 28.752,34.935 28.741,34.935 28.629,35.047 v3(28.612,35.047)
P1.04: U1.U24
P1.05: Q1.5 U1.T23 | length 38.6
  Top Layer w0.127: v2(15.342,5.385) 15.848,5.385 Q1.5@15.887,5.424 ; v2(18.39,6.807) 19.939,6.807 20.269,7.137 v2(20.269,7.185)
  Mid-Layer 1 w0.127: v2(15.342,5.385) 16.358,5.385 17.78,6.807 v2(18.39,6.807) ; v2(20.269,7.185) 20.269,8.941 29.231,17.903 29.231,33.795 29.231,34.804 29.231,34.945 28.629,35.547 v3(28.612,35.547)
P1.06: U1.R24 | length 0
  Top Layer w0.15: U1.R24@29.112,35.797 U1.R24@29.131,35.797
P1.07: Q1.2 U1.P23 | length 37.2
  Top Layer w0.127: Q1.2@17.777,5.424 18.404,5.424 18.517,5.537 18.517,6.198 18.799,6.48 20.12,6.48 20.746,7.106 v2(20.746,7.185)
  Mid-Layer 1 w0.127: v2(20.746,7.185) 20.746,7.225 20.523,7.448 20.523,8.836 29.485,17.798 29.485,34.186 29.485,34.909 29.485,35.191 28.629,36.047 v3(28.612,36.047)
P1.08: U1.P2 U3.3 | length 40.7
  Top Layer w0.127: U3.3@-1.88,42.574 -1.88,43.536 v2(-1.803,43.612) ; v2(1.585,35.297) 1.585,34.961 1.905,34.641 1.905,34.094 3.842,32.157 3.842,32.156 4.149,31.848 6.722,31.848 7.081,32.207 v2(8.534,32.207) ; v2(10.185,32.487) 10.329,32.343 17.63,32.343 19.079,33.792 19.495,33.792 20.286,34.582 20.286,35.049 v2(20.508,35.272)
  Mid-Layer 1 w0.127: v2(-1.803,43.612) 2.286,43.612 3.835,42.062 3.835,37.817 1.585,35.566 v2(1.585,35.297) ; v2(8.534,32.207) 9.906,32.207 v2(10.185,32.487) ; v2@20.508,35.277 22.259,35.277 23.029,36.047 v2(23.112,36.047)
P1.09: U1.R1
P1.10: U1.A20
P1.11: SW4.8 U1.B19 | length 49.3
  Top Layer w0.127: v1(-4.74,51.01) -4.74,47.234 -4.572,47.066 -2.159,47.066 v2(-1.549,46.457) ; v2(17.272,43.51) 18.601,43.51 23.707,48.616 26.365,48.616 v2(26.518,48.463)
  Mid-Layer 1 w0.127: v2(-1.549,46.457) -0.911,45.818 7.446,45.818 9.529,43.736 16.742,43.736 16.967,43.51 v2(17.272,43.51) ; v2(26.518,48.463) 26.518,40.437 27.362,39.593 v3(27.362,39.297)
  Bottom Layer w0.127: SW4.8@-4.946,51.911 -4.946,51.174 -4.782,51.01 v1(-4.74,51.01)
P1.12: SW4.6 U1.B17 | length 44.1
  Top Layer w0.127: v1(-4.135,46.106) -3.647,46.595 -2.399,46.595 v2(-2.032,46.228) ; v2(16.51,43.078) 18.604,43.078 23.71,48.184 25.768,48.184 26,47.952 v2(26.061,47.952)
  Mid-Layer 1 w0.127: v2(-2.032,46.228) -1.368,45.564 7.318,45.564 9.408,43.475 15.384,43.475 15.781,43.078 v2(16.51,43.078) ; v2(26.061,47.952) 26.068,47.945 26.068,40.335 26.862,39.541 v3(26.862,39.297)
  Bottom Layer w0.127: SW4.6@-5.054,45.7 -4.541,45.7 v1(-4.135,46.106)
P1.13: U1.A16 U4.3 | length 33.3
  Top Layer w0.127: v1(10.516,37.363) 10.947,37.363 11.149,37.162 U4.3@11.149,36.339 ; v1(22.631,45.085) 22.631,46.63 23.601,47.6 25.781,47.6 26.154,47.227 26.154,40.255 U1.A16@26.612,39.797
  Mid-Layer 1 w0.127: v1(10.516,37.363) 10.516,36.884 11.386,36.014 12.443,36.014 13.374,36.945 13.374,37.577 14.656,38.859 14.656,39.141 14.986,39.472 16.44,39.472 17.964,40.996 18.548,40.996 18.898,41.345 18.898,43.485 19.148,43.736 19.58,43.736 20.624,44.78 22.428,44.78 22.631,44.983 v1(22.631,45.085)
P1.14: SW3.3 U1.B15 | length 25.4
  Mid-Layer 1 w0.127: SW3.3@23.484,63.547 25.654,61.377 25.654,40.267 26.362,39.559 v3(26.362,39.297)
P1.15: SW2.3 U1.A14 | length 26.3
  Top Layer w0.127: v2(25.251,59.106) 25.293,59.106 25.547,59.36 SW2.3@29.984,63.797 ; v2(25.262,47.193) 25.273,47.193 25.866,46.6 25.866,40.043 U1.A14@26.112,39.797
  Mid-Layer 1 w0.127: v2(25.251,59.106) 25.262,59.095 v2(25.262,47.193)
RF: C4.2 C27.1 L1.2 | length 1.3
  Top Layer w0.762: L1.2@32.379,37.309 33.009,37.309 33.299,37.019 33.299,36.733
SWDCLK: J2.9 U1.AA24 | length 43.3
  Top Layer w0.127: J2.9@9.5,1.2 9.5,2.464 9.872,2.836 9.872,3.03 10.13,3.288 10.323,3.288 10.487,3.451 12.051,3.451 14.136,5.536 14.136,6.517 15.235,7.616 16.216,7.616 17.027,8.427 17.117,8.517 ; 17.117,8.518 17.119,8.52 17.277,8.52 v2(17.305,8.549) ; v2(28.6,28.064) 29.366,28.829 29.366,33.554 29.44,33.628 29.44,33.933 29.112,34.261 U1.AA24@29.112,34.297
  Mid-Layer 1 w0.127: v2(17.305,8.549) 17.334,8.577 17.334,9.05 28.723,20.44 28.723,27.941 v2(28.6,28.064)
SWDIO: J2.8 U1.AC24 | length 43
  Top Layer w0.127: J2.8@8.7,1.2 8.7,2.264 10.142,3.705 11.946,3.705 13.882,5.641 13.882,6.622 15.129,7.87 16.111,7.87 16.773,8.532 16.863,8.623 16.863,8.7 16.94,8.7 16.968,8.728 v2(16.968,8.886) ; v2(28.55,28.648) 28.6,28.648 29.112,29.159 U1.AC24@29.112,33.797
  Mid-Layer 1 w0.127: v2(16.968,8.886) 16.968,9.044 28.469,20.545 28.469,27.534 28.235,27.769 28.235,28.333 v2(28.55,28.648)
VBAT: C26.2 C44.1 C48.2 J2.15 Q6.4 R13.2 R24.1 SB4.2 TP21.1 U3.10 U4.4 U5.6 U10.1 | length 75.6
  Top Layer w0.381: C44.1@10.589,35.689 U4.4@11.149,35.689
  Top Layer w0.508: v1@-0.864,38.243 C26.2@-0.864,39.092 ; C26.2@-0.853,39.205 -0.853,40.579 ; v1(0.457,34.417) 0.457,34.087 v1(2.896,31.648) ; v1(6.7,7.987) J2.15@6.7,9.4 ; v1(9.621,33.858) 9.621,34.992 10.143,35.514 C44.1@10.414,35.514
  Mid-Layer 1 w0.508: v1(-0.864,38.227) -0.864,38.09 0.457,36.769 v1(0.457,34.417) ; v1(2.896,31.648) 6.274,31.648 8.484,33.858 v1(9.621,33.858) ; v1(3.2,6.423) 4.764,7.987 v1(6.7,7.987)
  Bottom Layer w0.229: v1@6.665,7.939 7.238,7.366 7.238,4.522 8.484,3.277 U10.1@8.484,2.076
  Bottom Layer w0.381: C48.2@4.2,32.634 U5.6@4.2,33.668
  Bottom Layer w0.508: -4.648,35.582 -3.708,34.642 -2.667,34.642 ; -4.648,35.811 -4.648,36.37 ; TP21.1@-4.648,37.871 -4.648,36.37 ; R24.1@-4.115,36.395 -4.623,36.395 -4.648,36.37 ; Q6.4@-2.68,35.204 -2.68,34.655 -2.667,34.642 ; v1@2.909,31.887 3.656,32.634 C48.2@4.2,32.634 ; v1(3.2,6.423) 3.2,6.499 0.533,9.166 0.533,16.226 0.515,16.245 0.515,16.809 0.533,16.828 0.533,34.29 0.181,34.642 -2.667,34.642 ; R13.2@8.685,35.133 9.491,35.133 9.754,34.871 9.754,33.991 v1(9.621,33.858)
VBAT_CON: J4.2 J5.3 Q7.4 R14.2 SW4.3 | length 31.8
  Top Layer w0.508: v1(-1.143,47.523) -0.864,47.244 -0.025,47.244 3.949,43.27 J4.2@3.949,39.746 3.949,38.723 4.369,38.303 5.766,38.303 6.426,37.643 J5.3@6.426,33.104
  Mid-Layer 1 w0.508: v1(-4.013,41.427) -4.013,45.136 -1.626,47.523 v1(-1.143,47.523)
  Bottom Layer w0.508: v1(-4.013,41.427) -4.293,41.148 -4.293,39.553 -3.818,39.078 Q7.4@-2.693,39.078 ; v1(-1.143,47.523) -0.965,47.701 SW4.3@0.379,47.701
VBAT_SW: J2.5 Q7.3 R12.2 SB4.1 SW4.2 SW4.4 TP14.1 U10.3 | length 71.4
  Top Layer w0.508: v4(0.508,18.567) 1.905,17.17 v1(2.921,17.17) ; J2.5@6.3,1.2 v1(6.3,2.867)
  Mid-Layer 1 w0.508: v1(-3.099,43.332) -3.277,43.155 -3.277,40.945 -2.784,40.452 -2.784,36.616 0.508,33.325 v4(0.508,18.567)
  Bottom Layer w0.229: v1(6.3,2.867) 6.887,2.867 7.188,2.565 7.188,1.765 7.442,1.511 U10.3@7.919,1.511
  Bottom Layer w0.381: 3.365,10.246 R12.2@6.012,10.246
  Bottom Layer w0.508: Q7.3@-1.143,39.078 -1.159,39.062 -1.753,39.062 -1.956,39.265 -1.956,40.538 -2.184,40.767 -2.682,40.767 -3.099,41.183 v1(-3.099,43.332) -3.099,43.51 -2.642,43.967 -1.586,43.967 -1.174,44.38 -1.174,45.183 -0.623,45.733 ; SW4.4@0.522,51.627 0.42,51.627 -1.908,49.298 -1.908,47.019 -0.623,45.733 ; SW4.2@0.589,45.733 -0.623,45.733 ; v1(2.921,17.17) 2.921,16.779 TP14.1@3.5,16.2 2.428,15.128 2.428,11.183 3.365,10.246 5.805,7.806 6.289,7.322 6.292,7.319 6.292,2.867 v1(6.3,2.867)
VBUS: C30.2 FB1.2 J2.3 Q7.2 R16.2 SB2.1 TP12.1 U8.3 | length 61.9
  Top Layer w0.381: v1(6.553,44.348) 6.553,44.66 9.772,47.879 11.114,47.879 C30.2@11.717,47.276 11.705,47.265 FB1.2@11.705,46.393
  Top Layer w0.508: v1(4.572,2.87) 4.7,2.742 J2.3@4.7,1.2
  Bottom Layer w0.127: Q7.2@-1.143,39.634 -1.14,39.631 R16.2@-0.213,39.631 1.199,39.631 2.665,41.097 3.302,41.097
  Bottom Layer w0.229: v1@4.638,2.805 4.267,2.434 4.267,1.727 4.47,1.524 4.973,1.524 U8.3@4.986,1.511
  Bottom Layer w0.381: 1.903,37.322 1.158,36.577 1.158,16.875 1.158,16.179 1.158,9.877 4.394,6.64 4.394,3.175 4.467,3.102 4.467,3.1 4.572,2.995 v1(4.572,2.87) ; 1.905,37.324 3.302,38.721 3.302,41.097 v1(6.553,44.348)
VBUS_5V: C19.2 C21.1 J2.4 R3.2 R15.2 SB2.2 TP13.1 U1.AD2 U3.1 U8.1 | length 107.3
  Top Layer w0.127: R15.2@-2.696,45.857 -1.686,45.857 -0.831,45.002 C19.2@-0.831,44.069
  Top Layer w0.25: U1.AD2@23.112,33.297 23.081,33.267 23.081,33.263 22.987,33.169 22.987,31.797 C21.1@23.237,31.547 v1@24.286,31.547
  Top Layer w0.254: R3.2@-2.103,36.207 -1.868,36.207 -0.178,37.897 -0.178,43.416 C19.2@-0.831,44.069
  Top Layer w0.381: C19.2@-0.853,44.091 -0.831,44.069 -0.33,44.57 v1(-0.33,44.722) ; v1(13.056,46.914) 13.129,46.987 15.596,46.987 16.358,47.749 v1(17.805,47.749)
  Top Layer w0.508: J2.4@5.5,1.2 v1(5.5,2.867)
  Top Layer w0.61: -0.853,42.545 C19.2@-0.853,44.091
  Bottom Layer w0.229: v1(5.5,2.867) v1@5.5,2.851 ; U8.1@5.551,2.076 5.563,2.088 5.563,2.788 v1@5.5,2.851 ; 5.69,3.04 v1@5.5,2.851
  Bottom Layer w0.25: v1(17.805,47.749) 18.517,47.749 22.403,43.863 22.403,35.619 24.816,33.206 24.816,32.102 v1(24.409,31.696)
  Bottom Layer w0.381: v1@-0.33,44.755 1.397,44.755 2.997,46.355 5.486,46.355 7.29,44.552 ; 5.69,3.04 5.69,6.571 1.778,10.483 1.778,16.166 1.778,16.888 1.778,36.347 3.912,38.481 3.912,40.809 6.765,43.663 7.112,43.663 7.29,43.84 7.29,44.552 ; v1(13.056,46.914) 10.543,46.914 9.931,46.302 9.931,44.777 9.706,44.552 7.29,44.552
VDD_LED: J2.11 LED1.4 P3.11 SB3.2 TP18.1 U9.1 | length 30.5
  Top Layer w0.381: LED1.4@16.431,1.75 16.865,1.75 16.866,1.749 v1(17.348,1.749) ; v1(17.018,10.766) 18.815,10.766 19.25,11.201 P3.11@19.25,11.668
  Top Layer w0.508: v1(9.9,7.987) J2.11@9.9,9.4
  Bottom Layer w0.229: v1@9.961,8.012 9.961,7.674 9.961,4.618 11.416,3.163 U9.1@11.416,2.076
  Bottom Layer w0.508: 9.9,8.322 10.389,8.811 11.586,8.811 ; v1(17.018,10.766) 17.018,10.792 16.612,11.198 14.389,11.198 12.001,8.811 11.586,8.811 ; v1(17.348,1.749) 17.348,3.581 16.789,4.14 15.401,4.14 14.732,4.809 14.732,5.664 11.586,8.811
VDD_LED': C45.1 J2.12 SB3.1 TP17.1 U4.1 U9.3 | length 54.4
  Top Layer w0.381: U4.1@12.219,35.689 12.779,35.689 C45.1@12.954,35.514 13.406,35.514 v1(13.411,35.509)
  Top Layer w0.508: v1(9.1,7.998) J2.12@9.1,9.4
  Mid-Layer 1 w0.508: v1(9.1,7.998) 9.1,8.782 8.207,9.674 2.986,9.674 1.27,11.391 1.27,32.151 2.284,33.165 5.177,33.165 7.7,35.687 10.965,35.687 11.143,35.509 v1(13.411,35.509)
  Bottom Layer w0.229: v1@9.056,8.016 9.056,7.67 9.056,4.654 9.728,3.982 9.728,2.057 10.275,1.511 U9.3@10.851,1.511
VDD_nRF: C6.1 C7.1 C8.1 C12.1 C14.1 J2.2 SB1.2 TP11.1 U1.A22 U1.AD14 U1.AD23 U1.B1 U1.W1 U1.Y2 U7.1 | length 85.2
  Top Layer w0.25: v1(20.193,31.696) 20.342,31.547 C6.1@20.88,31.547 20.88,32.251 22.612,33.982 22.612,34.389 ; v1(20.337,41.147) 20.737,40.747 C14.1@20.737,40.272 21.637,40.272 U1.B1@22.612,39.297 ; U1.W1@22.612,34.797 22.612,34.389 ; U1.Y2@23.112,34.547 23.036,34.547 22.877,34.389 22.612,34.389 ; U1.AD14@26.112,33.297 26.112,33.006 25.883,32.777 C7.1@25.883,32.215 26.187,32.215 26.43,31.973 v1(26.43,31.592) ; U1.A22@28.112,39.797 28.112,41.42 v1(28.118,41.427) ; v1@28.536,31.96 28.281,32.215 C8.1@27.977,32.215 27.977,32.469 28.612,33.104 U1.AD23@28.612,33.297
  Top Layer w0.508: J2.2@3.9,1.2 v1(3.9,2.867)
  Mid-Layer 1 w0.25: v1(20.337,41.147) 22.9,43.71 v1(23.52,43.71)
  Mid-Layer 1 w0.508: v1(3.9,2.867) 3.9,4.554 5.642,6.296 10.362,6.296 11.43,7.364 v1@11.43,9.627
  Bottom Layer w0.229: U7.1@2.773,1.921 3.43,1.921 3.81,2.301 3.81,2.539 SB1.2@3.81,2.892
  Bottom Layer w0.25: v1@20.091,31.798 v1(20.193,31.696) 20.193,32.133 20.955,32.895 20.955,40.529 v1(20.337,41.147) ; TP11.1@20.853,31.036 25.148,31.036 25.705,31.592 v1(26.43,31.592) 26.76,31.922 v1(28.498,31.922) ; v1(23.52,43.71) 26.088,43.71 28.118,41.679 v1(28.118,41.427)
  Bottom Layer w0.508: v1(11.43,9.652) 11.43,10.947 21.234,20.752 21.234,30.655 20.853,31.036 v1(20.193,31.696)
VREG: C49.2 J2.1 R1.2 R2.2 R29.2 R30.2 SB1.1 SW4.7 TP10.1 U2.4 U2.5 U5.3 U5.8 U7.3 | length 100.1
  Top Layer w0.127: v2(8.204,18.615) 8.503,18.316 R1.2@8.503,18.226
  Top Layer w0.381: v1(-4.1,47.879) -4.064,47.915 -4.064,47.93 -3.404,48.59 -0.432,48.59 2.086,46.072 5.058,46.072 5.41,45.72 5.41,44.122 7.188,42.344 v1(7.188,41.656) ; v1(13.564,18.615) 13.812,18.367 R2.2@13.812,18.247
  Top Layer w0.508: v1(3.099,2.847) v1(3.099,2.847) J2.1@3.1,1.2
  Mid-Layer 1 w0.508: v1(3.099,2.847) 3.099,4.83 5.326,7.058 10.046,7.058 10.312,7.324 10.312,7.34 10.668,7.695 10.668,9.189 9.421,10.436 3.302,10.436 2.032,11.706 2.032,17.704 ; U2.5@9.934,30.337 10.82,31.223 ; U2.4@11.714,30.337 11.707,30.337 10.82,31.223 ; v1(13.564,18.615) 13.287,18.339 2.667,18.339 2.032,17.704 ; 2.032,17.704 2.032,31.775 2.689,32.433 6.071,32.433 7.214,33.576 v1(7.214,34.112) 7.849,34.747 9.83,34.747 10.82,33.757 10.82,31.223
  Bottom Layer w0.229: U7.3@2.053,1.511 2.04,1.524 1.608,1.524 1.362,1.771 1.362,2.962 1.793,3.393 2.51,3.393 v1@3.01,2.892
  Bottom Layer w0.254: v1@3.01,2.892 SB1.1@3.185,2.892
  Bottom Layer w0.381: SW4.7@-5.061,47.911 -4.85,47.7 -4.279,47.7 v1(-4.1,47.879)
  Bottom Layer w0.508: 6.925,35.083 6.925,37.69 7.188,37.954 v1(7.188,41.656)
XC1: C1.1 U1.B24 X1.1 | length 5.5
  Top Layer w0.15: U1.B24@29.112,39.297 29.734,39.919 29.734,42.292 30.229,42.787 X1.1@30.545,42.787 ; C1.1@30.584,43.637 30.584,42.976 X1.1@30.47,42.862 X1.1@30.545,42.787 ; X1.1@30.757,42.575 X1.1@30.545,42.787
XC2: C2.1 U1.A23 X1.3 | length 3.7
  Top Layer w0.15: C2.1@28.198,42.031 28.701,42.031 X1.3@29.02,41.712 29.457,41.275 29.457,40.067 29.187,39.797 U1.A23@28.612,39.797
pads on no net: Fid1.0 Fid2.0 J1.4 J1.6@8.581,48.123 J1.6@15.181,48.123 J2. J2.13 J2.14 J2.18 J2.19 J3.0 J3.1 J3.3 J3.5 J4.0 J5.0 P3.0 P3.10 Q3.3 Q3.4 Q3.5 SW1.1 SW2.1 SW3.1 SW4.0 SW4.1 SW4.5 U1.AB2 U2.1 U2.2 U2.6 U2.14 U2.16 U5.5

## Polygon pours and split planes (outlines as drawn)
GND on Bottom Layer "Bottom_Layer-GND" (solid, remove dead copper, pour order 6): -33.706,-5.032 -33.706,82.979 50.114,82.979 50.114,-5.032
GND on Mid-Layer 1 "Mid_Layer_1-GND" (solid, remove dead copper, pour order 7): -29.077,-5.921 -29.077,86.749 53.93,86.749 53.93,-5.921
GND on Mid-Layer 2 "Mid_Layer_2-GND" (solid, remove dead copper, pour order 10): -36.037,-6.709 -36.037,84.826 47.783,84.826 47.783,-6.709
GND on Top Layer "Top_Layer-GND" (solid, remove dead copper, pour order 8): -30.155,-10.112 -30.155,84.237 53.665,84.237 53.665,-10.112

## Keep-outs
Top Layer:
  circle w0.1: c5,13.02 r2.44
  lines w0.127: -5.2,42.697 -5.2,52.553 ; 2.77,53.322 ccw(c3.285,50.875) 3.284,48.375
Mid-Layer 1:
  lines w0.127: -5.2,42.901 -5.2,52.451 ; 2.77,53.322 ccw(c3.285,50.875) 3.284,48.375
Mid-Layer 2:
  lines w0.127: 2.77,53.322 ccw(c3.285,50.875) 3.284,48.375 ; -5.207,52.349 -5.2,42.977 -5.207,52.349
Keep-Out Layer:
  circle w0.1: c-8.216,73.175 r2.44
  lines w0.127: -11.201,73.648 cw(c-8.216,73.175) -8.216,76.197 2.769,76.197 2.77,53.322 ccw(c3.285,50.875) 1.3,52.396 ; -11.2,73.648 -11.2,53.82 -5.2,53.82 -5.2,52.426 ; -5.2,42.977 -5.2,34.02 -1.577,34.02 cw(c-1.577,32.443) 0,32.443 0,0 21.9,0 21.9,8.92 28,15.02 30.886,15.02 ccw(c30.987,19.322) 35.133,18.172 ccw(c-57.806,37.826) 35.307,56.641 35.307,60.182 32.931,62.558 ; -5.2,44.399 -5.2,45.009 ; -5.2,46.406 -5.2,46.99 ; -5.2,48.397 -5.2,51.003 ; 0.788,51.006 ccw(c3.285,50.875) 3.284,48.375 ; 3.285,48.375 5.284,48.375 6.504,49.597 20.798,49.597 20.798,76.197 29.931,76.197 cw(c29.931,73.197) 32.931,73.197 32.931,62.558 ; 29.516,57.612 cw(c-57.806,37.826) 31.716,39.389 ; 30.273,59.9 32.931,62.558 ; 31.689,35.151 cw(c-57.806,37.826) 31.191,28.023 33.546,27.608 36.576,27.073 ; 17.784,34.85 19.284,34.85 19.284,38.85 17.784,38.85 17.784,34.85

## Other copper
Top Layer:
  pour cut-out: 34.567,35.493 34.567,33.993 32.067,33.993 32.067,35.493
  pour cut-out: 33.43,37.538 33.43,39.316 31.75,39.316 31.75,40.078 34.671,40.078 34.671,37.538
  pour cut-out: 29.194,36.223 31.937,36.223 31.937,38.072 31.137,38.072 31.137,39.118 29.194,39.118
  pour cut-out: 21.362,30.297 21.362,31.797 23.862,31.797 23.862,30.297
  pour cut-out: 26.112,35.797 26.112,37.297 28.612,37.297 28.612,35.797
Mid-Layer 1:
  pour cut-out: 0.965,11.042 0.211,11.042 0.211,11.422 0.229,11.405 0.816,11.405
  pour cut-out: 21.184,8.992 21.717,8.992 21.717,9.118 21.819,9.219 21.665,9.373 21.336,9.373 21.336,9.287 21.107,9.059
  pour cut-out: 28.01,15.322 27.686,15.646 27.33,15.291 27.508,15.113 27.933,15.113
  pour cut-out: 33.782,37.538 33.782,39.316 31.75,39.316 31.75,40.078 34.671,40.078 34.671,37.538
  pour cut-out: 37.477,35.322 29.982,35.322 29.982,39.322 37.477,39.322
Mid-Layer 2:
  pour cut-out: 33.782,37.538 33.782,39.316 31.75,39.316 31.75,40.078 34.671,40.078 34.671,37.538
  pour cut-out: 37.477,35.322 29.982,35.322 29.982,39.322 37.477,39.322
Bottom Layer:
  rectangle net NetU5_1: 2.972,33.652 3.607,35.455
  rectangle net VREG: 5.893,33.677 7.925,35.836
  rectangle net VREG: 5.131,35.455 7.925,35.963
  rectangle net NetU5_1: 2.972,35.455 4.369,35.963
  pour cut-out: 9.587,41.351 8.868,42.07 8.754,41.956 9.359,41.351
  pour cut-out: 7.645,43.174 7.417,43.403 7.391,43.403 7.29,43.301 7.523,43.068 7.595,43.068
  pour cut-out: -1.683,36.144 -2.134,36.144 -2.134,36.002 -2.108,35.977 -2.093,35.992 -1.626,35.992
  pour cut-out: 19.834,29.622 20.777,29.622 20.777,29.134 20.168,29.134 20.041,29.007
  pour cut-out: -5.639,46.38 -5.639,45.39 -5.863,45.39 -5.867,45.386 -5.918,45.437 -5.918,46.38
  pour cut-out: 33.223,33.601 36.95,37.328 35.183,39.096 31.455,35.369
  pour cut-out: 33.466,39.736 33.466,34.465 35.966,34.465 35.966,39.736
  pour cut-out: 33.782,37.538 33.782,39.316 31.75,39.316 31.75,40.078 34.671,40.078 34.671,37.538

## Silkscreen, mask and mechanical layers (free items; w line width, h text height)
Top Overlay:
  drawing of 953 lines, arcs and shapes, not listed
  text "Pb" at -1.209,73.242 h2.57
  text "'.PCBNumber'" at -10.588,55.643 h2.03
  text "'.PCBRevision'" at -10.538,54.424 h0.64
Bottom Overlay:
  text "Power" at -0.305,52.93 h2.03
Board Outline:
  lines w0.127: -1.577,34.02 -5.2,34.02 -5.2,53.82 -11.2,53.82 -11.2,73.648 -11.201,73.648 cw(c-8.216,73.175) -8.216,76.197 2.769,76.197 ; -1.538,34.02 cw(c-1.577,32.443) 0,32.482 ; 0,32.443 0,0 21.9,0 21.9,8.92 28,15.02 30.378,15.02 30.886,15.02 ccw(c30.986,19.321) 35.133,18.172 ccw(c-57.806,37.826) 35.307,56.641 35.307,60.182 32.931,62.558 32.931,73.197 ; 2.769,76.197 2.769,76.197 ; 2.769,76.197 2.77,53.322 ccw(c3.285,50.875) 3.284,48.375 ; 3.284,48.375 3.284,48.375 ; 3.284,48.375 5.284,48.375 6.504,49.597 20.798,49.597 ; 20.798,49.597 20.798,49.597 ; 20.798,49.597 20.798,76.197 ; 20.798,76.197 20.798,76.197 ; 20.798,76.197 29.931,76.197 ; 29.931,76.197 cw(c29.931,73.197) 32.931,73.197 ; 29.931,76.197 29.931,76.197 ; 32.931,73.197 32.931,73.197 ; 17.784,34.85 17.784,38.85 19.284,38.85 19.284,34.85 17.784,34.85
Top Assembly:
  drawing of 40 lines, arcs and shapes, not listed
Bottom Placement:
  region: 2.423,27.6 0.423,27.6 0.423,22.4 2.423,22.4
  region: 22.7,27.6 19.9,27.6 19.9,22.4 22.7,22.4
  region: 19.55,9.52 19.55,16.52 18.05,16.52 18.05,9.52
  rectangle: 0,12.27 3.25,13.77
  region: -2.5,61.95 -11.416,61.95 -11.416,60.45 -2.5,60.45
  region: 29.5,61.95 20.584,61.95 20.584,60.45 29.5,60.45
